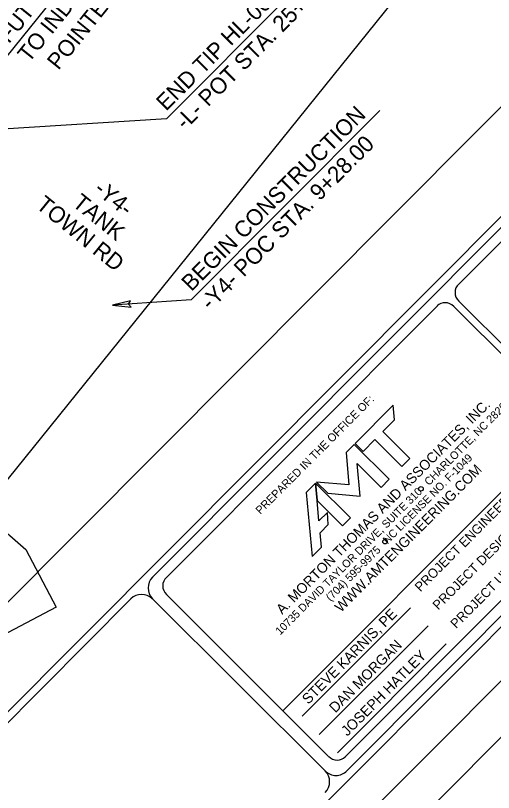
# Model space of a CAD drawing. Extents: x 1484850 to 1495577, y 495475 to 506245.
# Drawn here: x 1488945 to 1489886, y 498015 to 499545 of the extents above; entities that cross this region are included whole.
import ezdxf

# ---------------------------------------------------------------- set-up
doc = ezdxf.new("R2010")
doc.units = 0
for name, color, linetype in [('Exist Utilities Power UG Cable SUE LOS C', 7, 'Continuous'), ('Exist Utilities Sanitary Sewer Manhole CELL', 7, 'Continuous'), ('Exist Utilities Telephone UG Cable SUE LOS C', 7, 'Continuous'), ('Exist Utilities Telephone UG FO SUE LOS B', 7, 'Continuous'), ('Exist Utilities Telephone UG FO SUE LOS C', 7, 'Continuous'), ('Exist Utilities Water Meter CELL', 7, 'Continuous'), ('Exist Utilities Water UG Line SUE LOS B', 7, 'Continuous'), ('Exist Utilities Water Valve CELL', 7, 'Continuous'), ('P Pole (Pow Co) CELL', 7, 'Continuous'), ('Prop Guy Wire', 7, 'Continuous'), ('Prop UG Pow Cables', 7, 'Continuous')]:
    doc.layers.add(name, color=color, linetype=linetype)

msp = doc.modelspace()

# ---------------------------------------------------------------- linework, layer by layer
at = {"layer": 'Exist Utilities Power UG Cable SUE LOS C'}
for p, q in [((1489817.3, 499015.9), (1490303.9, 499504.3)), ((1490136.4, 498664.2), (1489817.4, 498982.6)), ((1489241.9, 498438.1), (1489775.4, 498973.4)), ((1490127.2, 498653.8), (1489807.5, 498972.2)), ((1489471.5, 498176.2), (1490037.3, 498743.3)), ((1489593.9, 498085.2), (1490128.2, 498621.2)), ((1489561.5, 498086.2), (1489242.2, 498405)), ((1489509.1, 498165.5), (1489722.2, 498378.4)), ((1489543.1, 498129.1), (1489757.3, 498343.3)), ((1489578.6, 498093.3), (1489793, 498307.6))]:
    msp.add_line(p, q, dxfattribs=at)
for centre, ratio, start_param, end_param in [((1489833.1, 498998.3), 0.941469, 6.214848, 7.853383), ((1489792, 498956.6), 0.930867, 4.711814, 6.283034), ((1489258, 498420.7), 0.941469, 6.214848, 7.853383), ((1489577.3, 498102), 0.941469, 1.570198, 3.141359)]:
    msp.add_ellipse(centre, major_axis=(-16.8, 16.7), ratio=ratio, start_param=start_param, end_param=end_param, dxfattribs=at)
at = {"layer": 'Exist Utilities Sanitary Sewer Manhole CELL'}
msp.add_lwpolyline([(1489171.9, 498983.1), (1489136.4, 498974.5), (1489173, 498970.5), (1489168, 498976.6)], close=True, dxfattribs=at)
at = {"layer": 'Exist Utilities Telephone UG Cable SUE LOS C'}
msp.add_lwpolyline([(1486945.7, 498451.8), (1488980.9, 500495.4), (1490008.1, 499472.4), (1487973, 497428.8)], close=True, dxfattribs=at)
msp.add_lwpolyline([(1486945.7, 498451.8), (1488980.9, 500495.4), (1490008.1, 499472.4), (1487973, 497428.8)], close=True, dxfattribs=at)
at = {"layer": 'Exist Utilities Telephone UG FO SUE LOS B'}
for points in [[(1489721.3, 498672.7), (1489668.1, 498725.6), (1489690.9, 498748.5), (1489688.3, 498777.5), (1489613.6, 498702.4), (1489629.4, 498686.7), (1489652.4, 498709.8), (1489705.5, 498656.9), (1489721.3, 498672.7)], [(1489623.5, 498598.8), (1489617.7, 498662.8), (1489664.8, 498615.9), (1489680.5, 498631.8), (1489611.6, 498700.4), (1489595.8, 498684.6), (1489601.1, 498621.1), (1489537.8, 498626.3), (1489559.8, 498604.5), (1489623.5, 498598.8)], [(1489538.6, 498590.1), (1489535.8, 498624.3), (1489517.4, 498605.9), (1489529.3, 498479.9), (1489547.2, 498497.9), (1489544.5, 498526.1), (1489560.8, 498542.5), (1489559, 498566.7), (1489542.1, 498549.8), (1489538.6, 498590.1)], [(1489604.7, 498555.7), (1489535.8, 498624.3), (1489538.6, 498590.1), (1489589, 498539.9), (1489604.7, 498555.7)]]:
    msp.add_lwpolyline(points, dxfattribs=at)
for centre in [(1489743.3, 498613.1), (1489672.4, 498509.1)]:
    msp.add_circle(centre, 4.43, dxfattribs=at)
at = {"layer": 'Exist Utilities Telephone UG FO SUE LOS C'}
for points in [[(1488948.4, 500051.2), (1488813.3, 500160.1), (1488087.8, 499260.5), (1488879.1, 498569.1), (1489756.2, 499656.7), (1489073.9, 500206.9)], [(1487208.7, 498608.1), (1488222.1, 499143.2), (1488965.4, 498493.7), (1489025.4, 498380), (1487698.9, 497679.6)]]:
    msp.add_lwpolyline(points, close=True, dxfattribs=at)
at = {"layer": 'Exist Utilities Water Meter CELL'}
msp.add_line((1488926.4, 499461.8), (1489269, 499886.6), dxfattribs=at)
at = {"layer": 'Exist Utilities Water UG Line SUE LOS B'}
for p, q in [((1489598, 499698.5), (1489242.3, 499341.4)), ((1489662.4, 499358), (1489290.8, 498984.9)), ((1489242.3, 499341.4), (1488900.6, 499320)), ((1489290.8, 498984.9), (1489136.4, 498974.5))]:
    msp.add_line(p, q, dxfattribs=at)
at = {"layer": 'P Pole (Pow Co) CELL'}
msp.add_lwpolyline([(1488481.3, 501486.1), (1484916.4, 497906.4), (1487254.7, 495577.9), (1490819.6, 499157.6)], close=True, dxfattribs=at)
at = {"layer": 'Prop Guy Wire'}
msp.add_lwpolyline([(1487337.5, 495550.5), (1490865.3, 499093), (1488622.4, 501326.5), (1485094.6, 497784)], close=True, dxfattribs=at)
at = {"layer": 'Prop UG Pow Cables'}
for p, q in [((1487288.8, 496526.2), (1490294.8, 499544.7)), ((1489214.9, 498439.1), (1490305.4, 499534.1)), ((1488248.5, 497469), (1489172, 498396.3)), ((1489214.6, 498396.3), (1489554.7, 498057.5)), ((1489554.7, 498057.5), (1489215, 498396.7))]:
    msp.add_line(p, q, dxfattribs=at)
for points in [[(1487576.3, 496007), (1490709.3, 499153.1)], [(1489597.1, 498057.6), (1490688, 499153.1)]]:
    msp.add_lwpolyline(points, dxfattribs=at)
for centre, start, end in [((1489236.2, 498417.9), 135.1191, 225.048), ((1489193.3, 498375.1), 45.1191, 135.1191), ((1489533.4, 498036.4), 315.1191, 45.1191), ((1489575.9, 498078.8), 225.048, 315.1191)]:
    msp.add_arc(centre, 30, start, end, dxfattribs=at)

# ---------------------------------------------------------------- texts
at = {"layer": 'Exist Utilities Power UG Cable SUE LOS C'}
for s, height, p in [('PREPARED IN THE OFFICE OF:', 15.971, (1489427.2, 498561.7)), ('PROJECT DESIGN ENGINEER', 18.545, (1489777.1, 498373.4)), ('PROJECT UTILITY COORDINATOR', 18.545, (1489812.2, 498337)), ('PROJECT ENGINEER', 18.545, (1489742.2, 498409.2)), ('STEVE KARNIS, PE', 20.399, (1489521.4, 498187.6)), ('DAN MORGAN', 20.4, (1489574.7, 498170.7)), ('JOSEPH HATLEY', 20.399, (1489598.3, 498124.9))]:
    msp.add_text(s, height=height, rotation=45.1044, dxfattribs=at).set_placement(p)
at = {"layer": 'Exist Utilities Telephone UG FO SUE LOS B'}
for s, height, p in [('10735 DAVID TAYLOR DRIVE, SUITE 310   CHARLOTTE, NC 28262', 15.512, (1489466.1, 498324.2)), ('A. MORTON THOMAS AND ASSOCIATES, INC.', 19.945, (1489470.2, 498364.5)), ('(704) 595-9975   NC LICENSE NO. F-1049', 15.512, (1489565.1, 498390.7)), ('WWW.AMTENGINEERING.COM', 19.945, (1489585.5, 498368.7))]:
    msp.add_text(s, height=height, rotation=45.1191, dxfattribs=at).set_placement(p)
at = {"layer": 'Exist Utilities Water Meter CELL'}
for s, rotation, p in [('FUTURE EXTENSION', 51.1158, (1488932.5, 499488.1)), ('TO INDEPENDENCE', 51.1158, (1488971.8, 499450.4)), ('POINTE PARKWAY', 51.1158, (1489029.7, 499435.9)), ('-L- POT STA. 25+30.00', 45.1191, (1489279, 499318.1)), ('END TIP HL-0025', 45.1191, (1489241.6, 499355.3)), ('BEGIN CONSTRUCTION', 45.1191, (1489291.4, 499000.1)), ('-Y4- POC STA. 9+28.00', 45.1191, (1489328.8, 498962.9))]:
    msp.add_text(s, height=32, rotation=rotation, dxfattribs=at).set_placement(p)
at = {"layer": 'Exist Utilities Water Valve CELL'}
for s, p in [('-Y4-', (1489097.8, 499198.8)), ('TANK', (1489055.2, 499171.6)), ('TOWN RD', (1488983.8, 499167.6))]:
    msp.add_text(s, height=32, rotation=320.9673, dxfattribs=at).set_placement(p)

doc.saveas('drawing.dxf')
